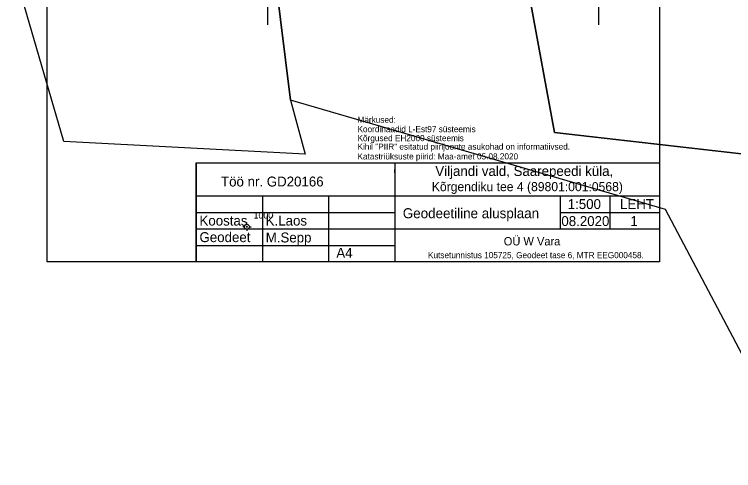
# Model space of a CAD drawing. Extents: x 598011 to 598230, y 6478330 to 6478537.
# Drawn here: x 598011.8 to 598120.4, y 6478330.1 to 6478399.1 of the extents above; entities that cross this region are included whole.
import ezdxf

# ---------------------------------------------------------------- set-up
doc = ezdxf.new("R2010")
doc.units = 0
for name, color, linetype in [('ALUSVORK', 7, 'Continuous'), ('MOOTMPUNKT', 7, 'Continuous'), ('PIIR', 7, 'Continuous'), ('VORK', 7, 'Continuous'), ('VORMISTUS', 7, 'Continuous')]:
    doc.layers.add(name, color=color, linetype=linetype)

msp = doc.modelspace()

# ---------------------------------------------------------------- linework, layer by layer
at = {"layer": 'ALUSVORK'}
for p, q in [((598046.91, 6478367.34), (598046.91, 6478367.59)), ((598046.54, 6478366.96), (598046.29, 6478366.96)), ((598046.91, 6478366.59), (598046.91, 6478366.34)), ((598047.29, 6478366.96), (598047.54, 6478366.96))]:
    msp.add_line(p, q, dxfattribs=at)
for radius in [0.375, 0.022]:
    msp.add_circle((598046.91, 6478366.96), radius, dxfattribs=at)
at = {"layer": 'MOOTMPUNKT'}
msp.add_circle((598046.91, 6478366.96), 0.075, dxfattribs=at)
at = {"layer": 'PIIR'}
for points in [[(598011.79, 6478405.5), (598081.48, 6478537.03), (598087.81, 6478533.61), (598081.1, 6478522.41), (598073.68, 6478503.38), (598068.04, 6478490.52), (598063.74, 6478475.61), (598063.42, 6478466.37), (598055.37, 6478465.26), (598054.72, 6478435.22), (598057.87, 6478421.2), (598067.5, 6478424), (598075.6, 6478425.87), (598075.95, 6478425.95), (598080.86, 6478427.08), (598083.16, 6478418.05), (598077.61, 6478417.15), (598069.31, 6478414.97), (598050.5, 6478410.56), (598053.52, 6478386.1), (598055.7, 6478377.93), (598019.25, 6478379.83)], [(598093.38, 6478381.19), (598086.49, 6478418.82), (598083.16, 6478418.05), (598080.86, 6478427.08), (598077.2, 6478441.43), (598071.55, 6478454.2), (598069.29, 6478462.69), (598069.71, 6478474.66), (598073.69, 6478488.47), (598079.22, 6478501.09), (598086.45, 6478519.6), (598092.94, 6478530.49), (598127.2, 6478509.56), (598154.27, 6478492.13), (598192.62, 6478466.21), (598223.81, 6478441.55), (598229.65, 6478435.94), (598191.25, 6478412.44), (598173.37, 6478396.18), (598161.58, 6478385.58), (598151.68, 6478381.11), (598144.54, 6478375.38)], [(598130.96, 6478330.09), (598110.14, 6478369.56), (598053.52, 6478386.1), (598050.5, 6478410.56), (598069.31, 6478414.97), (598077.61, 6478417.15), (598083.16, 6478418.05), (598086.49, 6478418.82), (598093.38, 6478381.19), (598154.28, 6478374.27), (598158.87, 6478339.87), (598159.68, 6478333.85)]]:
    msp.add_lwpolyline(points, close=True, dxfattribs=at)
at = {"layer": 'VORK'}
for p, q in [((598050, 6478402.5), (598050, 6478397.5)), ((598100, 6478402.5), (598100, 6478397.5))]:
    msp.add_line(p, q, dxfattribs=at)
at = {"layer": 'VORMISTUS'}
for p, q in [((598039.25, 6478376.64), (598109.25, 6478376.64)), ((598039.25, 6478376.64), (598039.25, 6478361.64)), ((598069.25, 6478376.64), (598069.25, 6478361.64)), ((598109.25, 6478376.64), (598109.25, 6478361.64)), ((598069.25, 6478375.14), (598069.25, 6478375.64)), ((598039.25, 6478371.64), (598109.25, 6478371.64)), ((598049.25, 6478371.64), (598049.25, 6478361.64)), ((598059.25, 6478371.64), (598059.25, 6478361.64)), ((598094.25, 6478371.64), (598094.25, 6478366.64)), ((598101.75, 6478371.64), (598101.75, 6478366.64)), ((598039.25, 6478369.14), (598069.25, 6478369.14)), ((598094.25, 6478369.14), (598109.25, 6478369.14)), ((598039.25, 6478366.64), (598109.25, 6478366.64)), ((598039.25, 6478364.14), (598069.25, 6478364.14)), ((598109.25, 6478361.64), (598039.25, 6478361.64))]:
    msp.add_line(p, q, dxfattribs=at)
msp.add_lwpolyline([(598109.25, 6478361.64), (598016.75, 6478361.64), (598016.75, 6478504.14), (598109.25, 6478504.14), (598109.25, 6478361.64)], dxfattribs=at)
msp.add_lwpolyline([(598109.25, 6478361.64), (598039.25, 6478361.64), (598039.25, 6478376.64), (598109.25, 6478376.64)], close=True, dxfattribs=at)

# ---------------------------------------------------------------- texts
at = {"layer": 'ALUSVORK'}
msp.add_text('1000', height=1, dxfattribs=at).set_placement((598047.91, 6478368.21))
at = {"layer": 'VORMISTUS'}
for s, height, p in [('Märkused:', 0.927, (598063.62, 6478382.68)), ('Koordinaadid L-Est97 süsteemis', 0.9271, (598063.62, 6478381.26)), ('Kõrgused EH2000 süsteemis', 0.9271, (598063.62, 6478379.9)), ('Viljandi vald, Saarepeedi küla,', 1.5, (598075.37, 6478374.64)), ('Töö nr. GD20166', 1.5, (598043, 6478373.05)), ('Kõrgendiku tee 4 (89801:001:0568)', 1.3718, (598074.84, 6478372.34)), ('1:500', 1.5, (598095.37, 6478369.64)), ('LEHT', 1.5, (598103.27, 6478369.64)), ('Geodeetiline alusplaan', 1.513, (598070.46, 6478368.25)), ('Koostas', 1.5, (598039.75, 6478367.14)), ('K.Laos', 1.5, (598049.75, 6478367.14)), ('08.2020', 1.5, (598094.41, 6478367.07)), ('1', 1.5, (598104.84, 6478367.07)), ('Geodeet', 1.5, (598039.75, 6478364.64)), ('M.Sepp', 1.5, (598049.75, 6478364.59)), ('OÜ W Vara', 1.25, (598085.71, 6478364.14)), ('A4', 1.5, (598060.42, 6478362.27)), ('Kutsetunnistus 105725, Geodeet tase 6, MTR EEG000458.', 0.9271, (598074.27, 6478362.21))]:
    msp.add_text(s, height=height, rotation=360, dxfattribs=at).set_placement(p)
for s, p in [('Kihil "PIIR" esitatud piirijoonte asukohad on informatiivsed.', (598063.62, 6478378.62)), ('Katastriüksuste piirid: Maa-amet 05.08.2020', (598063.62, 6478377.14))]:
    msp.add_text(s, height=0.9271, dxfattribs=at).set_placement(p)

doc.saveas('drawing.dxf')
